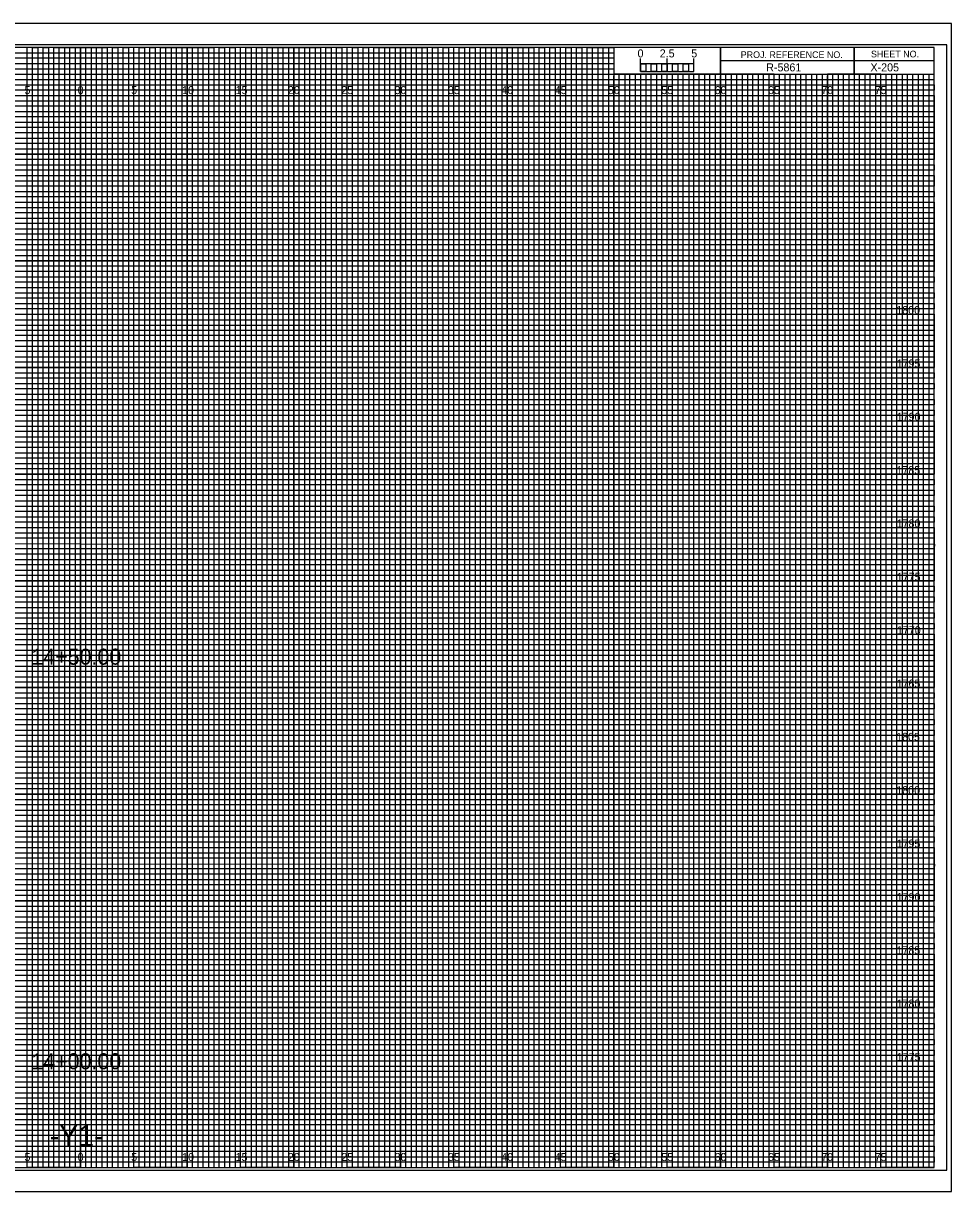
# Model space of a CAD drawing. Extents: x -7 to 162, y -2 to 767.
# Drawn here: x 74.6 to 161.7, y 437.7 to 547.2 of the extents above; entities that cross this region are included whole.
import ezdxf

# ---------------------------------------------------------------- set-up
doc = ezdxf.new("R2010")
doc.units = 0
for name, color, linetype in [('Prop Grid Mask', 7, 'Continuous'), ('Prop XS Alignment Label', 7, 'Continuous'), ('Prop XS Bar Scale Labels', 7, 'Continuous'), ('Prop XS Elevation Labels', 7, 'Continuous'), ('Prop XS Project Number', 7, 'Continuous'), ('Prop XS Sheet Number', 7, 'Continuous'), ('Prop XS Station Labels', 7, 'Continuous'), ('Sheet Cross Section CELL', 7, 'Continuous'), ('Sheet Cross Section Grid Major CELL', 7, 'Continuous'), ('Sheet Cross Section Grid Middle CELL', 7, 'Continuous'), ('Sheet Cross Section Grid Minor 1 CELL', 7, 'Continuous'), ('Sheet Cross Section Grid Minor 2 CELL', 7, 'Continuous'), ('Sheet Cross Section Scale CELL', 7, 'Continuous'), ('Sheet Cutting Line CELL', 7, 'Continuous'), ('Sheet DOT Grid CELL', 7, 'Continuous'), ('Sheet Plot Border Inside CELL', 7, 'Continuous'), ('Sheet Plot Border Outside CELL', 7, 'Continuous')]:
    doc.layers.add(name, color=color, linetype=linetype)

msp = doc.modelspace()

# ---------------------------------------------------------------- linework, layer by layer
at = {"layer": 'Sheet Cross Section CELL'}
for p, q in [((152.5, 545), (152.5, 542.5)), ((152.5, 542.5), (152.5, 545)), ((160, 543.75), (140, 543.75)), ((140, 543.75), (140, 542.5)), ((140, 542.5), (160, 542.5))]:
    msp.add_line(p, q, dxfattribs=at)
for points in [[(160, 545), (0, 545), (0, 440), (160, 440)], [(140, 545), (130, 545), (130, 542.51), (140, 542.51)], [(160, 545), (140, 545), (140, 542.5), (160, 542.5)]]:
    msp.add_lwpolyline(points, close=True, dxfattribs=at)
at = {"layer": 'Sheet Cross Section Grid Major CELL'}
for p, q in [((75, 545), (70, 545)), ((75, 440), (75, 545)), ((85, 545), (80, 545)), ((80, 545), (80, 440)), ((85, 440), (85, 545)), ((95, 545), (90, 545)), ((90, 545), (90, 440)), ((95, 440), (95, 545)), ((105, 545), (100, 545)), ((100, 545), (100, 440)), ((105, 440), (105, 545)), ((115, 545), (110, 545)), ((110, 545), (110, 440)), ((115, 440), (115, 545)), ((125, 545), (120, 545)), ((120, 545), (120, 440)), ((125, 440), (125, 545)), ((130, 545), (130, 440)), ((135, 440), (135, 542.5)), ((145, 542.5), (140, 542.5)), ((140, 542.5), (140, 440)), ((145, 440), (145, 542.5)), ((155, 542.5), (150, 542.5)), ((150, 542.5), (150, 440)), ((155, 440), (155, 542.5)), ((80, 440), (75, 440)), ((90, 440), (85, 440)), ((100, 440), (95, 440)), ((110, 440), (105, 440)), ((120, 440), (115, 440)), ((130, 440), (125, 440)), ((140, 440), (135, 440)), ((150, 440), (145, 440)), ((160, 440), (155, 440)), ((160, 440), (160, 440))]:
    msp.add_line(p, q, dxfattribs=at)
for points in [[(0, 540), (160, 540), (160, 535), (0, 535)], [(0, 530), (160, 530), (160, 525), (0, 525)], [(0, 520), (160, 520), (160, 515), (0, 515)], [(0, 510), (160, 510), (160, 505), (0, 505)], [(0, 500), (160, 500), (160, 495), (0, 495)], [(0, 490), (160, 490), (160, 485), (0, 485)], [(0, 480), (160, 480), (160, 475), (0, 475)], [(0, 470), (160, 470), (160, 465), (0, 465)], [(0, 460), (160, 460), (160, 455), (0, 455)], [(0, 450), (160, 450), (160, 445), (0, 445)]]:
    msp.add_lwpolyline(points, dxfattribs=at)
at = {"layer": 'Sheet Cross Section Grid Middle CELL'}
for points in [[(72.5, 440), (77.5, 440), (77.5, 545), (82.5, 545), (82.5, 440), (87.5, 440), (87.5, 545), (92.5, 545), (92.5, 440), (97.5, 440), (97.5, 545), (102.5, 545), (102.5, 440), (107.5, 440), (107.5, 545), (112.5, 545), (112.5, 440), (117.5, 440), (117.5, 545), (122.5, 545), (122.5, 440), (127.5, 440), (127.5, 545), (129.97, 545), (130, 545), (130, 542.5), (132.5, 542.5), (132.5, 440), (137.5, 440), (137.5, 542.5), (142.5, 542.5), (142.5, 440), (147.5, 440), (147.5, 542.5), (152.5, 542.5), (152.5, 440), (157.5, 440), (157.5, 542.5)], [(0, 542.5), (137.5, 542.5)], [(0, 532.5), (160, 532.5), (160, 537.5), (0, 537.5)], [(0, 522.5), (160, 522.5), (160, 527.5), (0, 527.5)], [(0, 512.5), (160, 512.5), (160, 517.5), (0, 517.5)], [(0, 502.5), (160, 502.5), (160, 507.5), (0, 507.5)], [(0, 492.5), (160, 492.5), (160, 497.5), (0, 497.5)], [(0, 482.5), (160, 482.5), (160, 487.5), (0, 487.5)], [(0, 472.5), (160, 472.5), (160, 477.5), (0, 477.5)], [(0, 462.5), (160, 462.5), (160, 467.5), (0, 467.5)], [(0, 452.5), (160, 452.5), (160, 457.5), (0, 457.5)], [(0, 442.5), (160, 442.5), (160, 447.5), (0, 447.5)]]:
    msp.add_lwpolyline(points, dxfattribs=at)
at = {"layer": 'Sheet Cross Section Grid Minor 1 CELL'}
for p, q in [((0, 544.5), (130, 544.5)), ((130, 544.5), (130, 543.99)), ((130, 543.99), (0, 543.99)), ((0, 543.5), (130, 543.5)), ((130, 543.5), (130, 542.95)), ((130, 542.95), (0, 542.95)), ((0, 542), (160, 542))]:
    msp.add_line(p, q, dxfattribs=at)
for points in [[(0, 541.5), (135, 541.5), (160, 541.5), (160, 541), (0, 541)], [(0, 540.5), (160, 540.5), (160, 539.5), (0, 539.5)], [(0, 539), (160, 539), (160, 538.5), (0, 538.49)], [(0, 538), (160, 538), (160, 537), (0, 537)], [(0, 536.5), (160, 536.5), (160, 536), (0, 536)], [(0, 535.5), (160, 535.5), (160, 534.5), (0, 534.5)], [(0, 534), (160, 534), (160, 533.5), (0, 533.5)], [(0, 533), (160, 533), (160, 532), (0, 532)], [(0, 531.5), (160, 531.5), (160, 531), (0, 531)], [(0, 530.5), (160, 530.5), (160, 529.5), (0, 529.5)], [(0, 529), (160, 529), (160, 528.5), (0, 528.5)], [(0, 528), (160, 528), (160, 526.98), (160, 526.5), (160, 526), (0, 526)], [(0, 527), (160, 527), (160, 526.5), (0, 526.5)], [(0, 525.5), (160, 525.5), (160, 524.5), (0, 524.51)], [(0, 524.51), (160, 524.5), (160, 524), (0, 524)], [(0, 523.5), (160, 523.5), (160, 523), (0, 523)], [(0, 522), (160, 522), (160, 521.5), (0, 521.5)], [(0, 521), (160, 521), (160, 520.5), (0, 520.5)], [(-0.04, 519.45), (160, 519.45), (160, 518.94), (-0.04, 518.94)], [(0, 518.5), (160, 518.5), (160, 518), (0, 518)], [(0, 517), (160, 517), (160, 516.5), (0, 516.5)], [(0, 516), (160, 516), (160, 515.5), (0, 515.5)], [(0, 514.5), (160, 514.5), (160, 514), (0, 514)], [(0, 513.5), (160, 513.5), (160, 513), (0, 513)], [(0, 512), (160, 512), (160, 511.5), (0, 511.5)], [(0, 511), (160, 511), (160, 510.5), (0, 510.5)], [(0, 509.5), (160, 509.5), (160, 508.99), (0, 509)], [(0, 508.5), (160, 508.5), (160, 508), (0, 508)], [(0, 507), (160, 507), (160, 506.5), (0, 506.5)], [(0, 506), (160, 506), (160, 505.5), (0, 505.5)], [(0, 504.5), (160, 504.5), (160, 504), (0, 504)], [(0, 503.5), (160, 503.5), (160, 503), (0, 503)], [(0, 502), (160, 502), (160, 501.5), (0, 501.5)], [(0, 501), (160, 501), (160, 500.5), (0, 500.5)], [(0, 499.5), (160, 499.5), (160, 499), (0, 499)], [(0, 498.5), (160.03, 498.45), (160, 498), (0, 498)], [(0, 497), (160, 497), (160, 496.5), (0, 496.5)], [(0, 496), (160, 496), (160, 495.5), (0, 495.5)], [(0, 494.5), (160, 494.5), (160, 494), (0, 494)], [(0, 493.5), (160, 493.5), (160, 493), (0, 493)], [(0, 492), (160, 492), (160, 491.5), (0, 491.5)], [(0, 491), (160, 491), (160, 490.5), (0, 490.5)], [(0, 489.5), (160, 489.5), (160, 489), (0, 489)], [(0, 488.5), (160, 488.5), (160, 488), (0, 488)], [(0, 487), (160, 487), (160, 486.5), (0, 486.5)], [(0, 486), (160, 486), (160, 485.5), (0, 485.5)], [(0, 484.5), (160, 484.5), (160, 484), (0, 484)], [(0, 483.5), (160, 483.5), (160, 483), (0, 483)], [(0, 482), (160, 482), (160, 481.5), (0, 481.5)], [(0, 481), (160, 481), (160, 480.5), (0, 480.5)], [(0, 479.5), (160, 479.5), (160, 478.99), (0, 479)], [(0, 478.5), (160, 478.5), (160, 478), (0, 478)], [(0, 477), (160, 477), (160, 476.5), (0, 476.5)], [(0, 476), (160, 476), (160, 475.5), (0, 475.5)], [(0, 474.5), (160, 474.5), (160, 474), (0, 474)], [(0, 473.5), (160, 473.5), (160, 473), (0, 473)], [(0, 472), (160, 472), (160, 471.5), (0, 471.5)], [(0, 471), (160, 471), (160, 470.5), (0, 470.5)], [(0, 469.5), (160, 469.5), (160, 469), (0, 469)], [(0, 468.5), (160.03, 468.45), (160, 468), (0, 468)], [(0, 467), (160, 467), (160, 466.5), (0, 466.5)], [(0, 466), (160, 466), (160, 465.5), (0, 465.5)], [(0, 464.5), (160, 464.5), (160, 464), (0, 464)], [(0, 463.5), (160, 463.5), (160, 463), (0, 463)], [(0, 462), (160, 462), (160, 461.5), (0, 461.5)], [(0, 461), (160, 461), (160, 460.5), (0, 460.5)], [(0, 459.5), (160, 459.5), (160, 459), (0, 459)], [(0, 458.5), (160, 458.5), (160, 458), (0, 458)], [(0, 457), (160, 457), (160, 456.5), (0, 456.5)], [(0, 456), (160, 456), (160, 455.5), (0, 455.5)], [(0, 454.5), (160, 454.5), (160, 454), (0, 454)], [(0, 453.5), (160, 453.5), (160, 453), (0, 453)], [(0, 452), (160, 452), (160, 451.5), (0, 451.5)], [(0, 451), (160, 451), (160, 450.5), (0, 450.5)], [(0, 449.5), (160, 449.5), (160, 449), (0, 449)], [(0, 448.5), (160, 448.5), (160, 448), (0, 448)], [(0, 447), (160, 447), (160, 446.5), (0, 446.5)], [(0, 446), (160, 446), (160, 445.5), (0, 445.5)], [(0, 444.5), (160, 444.5), (160, 444), (0, 444)], [(0, 443.5), (160, 443.5), (160, 443), (0, 443)], [(0, 442), (160, 442), (160, 441.5), (0, 441.5)], [(0, 441), (160, 441), (160, 440.5), (0, 440.5)]]:
    msp.add_lwpolyline(points, dxfattribs=at)
at = {"layer": 'Sheet Cross Section Grid Minor 2 CELL'}
for p, q in [((133.5, 542.5), (133, 542.5)), ((133, 542.5), (133, 440)), ((133.5, 440), (133.5, 542.5)), ((134.5, 542.5), (134, 542.5)), ((134, 542.5), (134, 440)), ((134.5, 440), (134.5, 542.5)), ((133, 440), (132.5, 440)), ((134, 440), (133.5, 440))]:
    msp.add_line(p, q, dxfattribs=at)
for points in [[(75, 440), (75.5, 440), (75.5, 545), (76, 545), (76, 440)], [(76, 440), (76.5, 440), (76.5, 545), (77, 545), (77, 440)], [(77.5, 440), (78, 440), (78, 545), (78.5, 545), (78.5, 440)], [(78.5, 440), (79, 440), (79, 545), (79.5, 545), (79.5, 440)], [(80, 440), (80.5, 440), (80.5, 545), (81, 545), (81, 440)], [(81, 440), (81.5, 440), (81.5, 545), (82, 545), (82, 440)], [(82.5, 440), (83, 440), (83, 545), (83.5, 545), (83.5, 440)], [(83.5, 440), (84, 440), (84, 545), (84.5, 545), (84.5, 440)], [(85, 440), (85.5, 440), (85.5, 545), (86, 545), (86, 440)], [(86, 440), (86.5, 440), (86.5, 545), (87, 545), (87, 440)], [(87.5, 440), (88, 440), (88, 545), (88.5, 545), (88.5, 440)], [(88.5, 440), (89, 440), (89, 545), (89.5, 545), (89.5, 440)], [(90, 440), (90.5, 440), (90.5, 545), (91, 545), (91, 440)], [(91, 440), (91.5, 440), (91.5, 545), (92, 545), (92, 440)], [(92.5, 440), (93, 440), (93, 545), (93.5, 545), (93.5, 440)], [(93.5, 440), (94, 440), (94, 545), (94.5, 545), (94.5, 440)], [(95, 440), (95.5, 440), (95.5, 545), (96, 545), (96, 440)], [(96, 440), (96.5, 440), (96.5, 545), (97, 545), (97, 440)], [(97.5, 440), (98, 440), (98, 545), (98.5, 545), (98.5, 440)], [(98.5, 440), (99, 440), (99, 545), (99.5, 545), (99.5, 440)], [(100, 440), (100.5, 440), (100.5, 545), (101, 545), (101, 440)], [(101, 440), (101.5, 440), (101.5, 545), (102, 545), (102, 440)], [(102.5, 440), (103, 440), (103, 545), (103.5, 545), (103.5, 440)], [(103.5, 440), (104, 440), (104, 545), (104.5, 545), (104.5, 440)], [(105, 440), (105.5, 440), (105.5, 545), (106, 545), (106, 440)], [(106, 440), (106.5, 440), (106.5, 545), (107, 545), (107, 440)], [(107.5, 440), (108, 440), (108, 545), (108.5, 545), (108.5, 440)], [(108.5, 440), (109, 440), (109, 545), (109.5, 545), (109.5, 440)], [(110, 440), (110.5, 440), (110.5, 545), (111, 545), (111, 440)], [(111, 440), (111.5, 440), (111.5, 545), (112, 545), (112, 440)], [(112.5, 440), (113, 440), (113, 545), (113.5, 545), (113.5, 440)], [(113.5, 440), (114, 440), (114, 545), (114.5, 545), (114.5, 440)], [(115, 440), (115.5, 440), (115.5, 545), (116, 545), (116, 440)], [(116, 440), (116.5, 440), (116.5, 545), (117, 545), (117, 440)], [(117.5, 440), (118, 440), (118, 545), (118.5, 545), (118.5, 440)], [(118.5, 440), (119, 440), (119, 545), (119.5, 545), (119.5, 440)], [(120, 440), (120.5, 440), (120.5, 545), (121, 545), (121, 440)], [(121, 440), (121.5, 440), (121.5, 545), (122, 545), (122, 440)], [(122.5, 440), (123, 440), (123, 545), (123.5, 545), (123.5, 440)], [(123.5, 440), (124, 440), (124, 545), (124.5, 545), (124.5, 440)], [(125, 440), (125.5, 440), (125.5, 545), (126, 545), (126, 440)], [(126, 440), (126.5, 440), (126.5, 545), (127, 545), (127, 440)], [(127.5, 440), (128, 440), (128, 545), (128.5, 545), (128.5, 440)], [(128.5, 440), (129, 440), (129, 545), (129.5, 545), (129.5, 440)], [(130, 440), (130.5, 440), (130.5, 542.5), (131.01, 542.5), (131.01, 440)], [(131, 440), (131.5, 440), (131.5, 542.5), (132, 542.5), (132, 440)], [(135, 440), (135.49, 440), (135.49, 542.5), (136, 542.5), (136, 440)], [(136, 440), (136.5, 440), (136.5, 542.5), (137.03, 542.5), (137.03, 440)], [(137.5, 440), (138, 440), (138, 542.5), (138.5, 542.5), (138.5, 440)], [(138.5, 440), (139, 440), (139, 542.5), (139.5, 542.5), (139.5, 440)], [(140, 440), (140.5, 440), (140.5, 542.5), (141, 542.5), (141, 440)], [(141, 440), (141.5, 440), (141.5, 542.5), (142, 542.5), (142, 440)], [(142.5, 440), (143, 440), (143, 542.5), (143.5, 542.5), (143.5, 440)], [(143.5, 440), (144, 440), (144, 542.5), (144.5, 542.5), (144.5, 440)], [(145, 440), (145.5, 440), (145.5, 542.5), (146, 542.5), (146, 440)], [(146, 440), (146.5, 440), (146.5, 542.5), (147, 542.5), (147, 440)], [(147.5, 440), (148, 440), (148, 542.5), (148.5, 542.5), (148.5, 440)], [(148.5, 440), (149, 440), (149, 542.5), (149.5, 542.5), (149.5, 440)], [(150, 440), (150.5, 440), (150.5, 542.5), (151, 542.5), (151, 440)], [(151, 440), (151.5, 440), (151.5, 542.5), (152, 542.5), (152, 440)], [(152.5, 440), (153, 440), (153, 542.5), (153.5, 542.5), (153.5, 440)], [(153.5, 440), (154, 440), (154, 542.5), (154.5, 542.5), (154.5, 440)], [(155, 440), (155.5, 440), (155.5, 542.5), (156, 542.5), (156, 440)], [(156, 440), (156.5, 440), (156.5, 542.5), (157, 542.5), (157, 440)], [(157.5, 440), (158, 440), (158, 542.5), (158.5, 542.5), (158.5, 440)], [(158.5, 440), (159, 440), (159, 542.5), (159.5, 542.5), (159.5, 440)]]:
    msp.add_lwpolyline(points, dxfattribs=at)
at = {"layer": 'Sheet Cross Section Scale CELL'}
for p, q in [((132.5, 542.75), (132.5, 543.95)), ((132.5, 543.45), (132.5, 543.95)), ((135, 542.75), (135, 543.95)), ((137.5, 542.75), (137.5, 543.95)), ((137.5, 543.45), (137.5, 543.95))]:
    msp.add_line(p, q, dxfattribs=at)
for points in [[(137.5, 543.45), (132.5, 543.45), (132.5, 542.75), (137.5, 542.75)], [(132.5, 543.45), (133, 543.45), (133, 542.75), (132.5, 542.75)], [(133.5, 543.45), (134, 543.45), (134, 542.75), (133.5, 542.75)], [(134.5, 543.45), (135, 543.45), (135, 542.75), (134.5, 542.75)], [(135.5, 543.45), (136, 543.45), (136, 542.75), (135.5, 542.75)], [(136.5, 543.45), (137, 543.45), (137, 542.75), (136.5, 542.75)]]:
    msp.add_lwpolyline(points, close=True, dxfattribs=at)
at = {"layer": 'Sheet Cutting Line CELL'}
for p, q in [((161.65, 547.25), (-6.7, 547.25)), ((-6.7, 437.75), (161.65, 437.75))]:
    msp.add_line(p, q, dxfattribs=at)
at = {"layer": 'Sheet DOT Grid CELL'}
for p, q in [((75, 440), (75, 545)), ((80, 440), (80, 545)), ((85, 440), (85, 545)), ((90, 440), (90, 545)), ((95, 440), (95, 545)), ((100, 440), (100, 545)), ((105, 440), (105, 545)), ((110, 440), (110, 545)), ((115, 440), (115, 545)), ((120, 440), (120, 545)), ((125, 440), (125, 545)), ((130, 440), (130, 542.34)), ((135, 440), (135, 542.34)), ((140, 440), (140, 542.34)), ((145, 440), (145, 542.34)), ((150, 440), (150, 542.34)), ((155, 440), (155, 542.34)), ((0, 540), (160, 540)), ((0, 535), (160, 535)), ((0, 530), (160, 530)), ((0, 525), (160, 525)), ((0, 520), (160, 520)), ((0, 515), (160, 515)), ((0, 510), (160, 510)), ((0, 505), (160, 505)), ((0, 500), (160, 500)), ((0, 495), (160, 495)), ((0, 490), (160, 490)), ((0, 485), (160, 485)), ((0, 480), (160, 480)), ((0, 475), (160, 475)), ((0, 470), (160, 470)), ((0, 465), (160, 465)), ((0, 460), (160, 460)), ((0, 455), (160, 455)), ((0, 450), (160, 450)), ((0, 445), (160, 445))]:
    msp.add_line(p, q, dxfattribs=at)
at = {"layer": 'Sheet Plot Border Inside CELL'}
msp.add_lwpolyline([(-5.4, 439.75), (161.2, 439.75), (161.2, 545.25), (-5.4, 545.25)], close=True, dxfattribs=at)
at = {"layer": 'Sheet Plot Border Outside CELL'}
msp.add_lwpolyline([(-6.7, 437.75), (161.65, 437.75), (161.65, 547.25), (-6.7, 547.25)], close=True, dxfattribs=at)

# ---------------------------------------------------------------- texts
at = {"layer": 'Prop Grid Mask'}
for s, p in [('5', (74.74, 540.62)), ('0', (79.73, 540.62)), ('0', (79.73, 540.62)), ('5', (84.74, 540.62)), ('10', (89.52, 540.62)), ('15', (94.53, 540.62)), ('20', (99.43, 540.62)), ('25', (104.44, 540.62)), ('30', (109.43, 540.62)), ('35', (114.44, 540.62)), ('40', (119.43, 540.62)), ('45', (124.44, 540.62)), ('50', (129.43, 540.62)), ('55', (134.44, 540.62)), ('60', (139.43, 540.62)), ('65', (144.44, 540.62)), ('70', (149.43, 540.62)), ('75', (154.44, 540.62)), ('5', (74.74, 440.62)), ('0', (79.73, 440.62)), ('0', (79.73, 440.62)), ('5', (84.74, 440.62)), ('10', (89.52, 440.62)), ('15', (94.53, 440.62)), ('20', (99.43, 440.62)), ('25', (104.44, 440.62)), ('30', (109.43, 440.62)), ('35', (114.44, 440.62)), ('40', (119.43, 440.62)), ('45', (124.44, 440.62)), ('50', (129.43, 440.62)), ('55', (134.44, 440.62)), ('60', (139.43, 440.62)), ('65', (144.44, 440.62)), ('70', (149.43, 440.62)), ('75', (154.44, 440.62))]:
    msp.add_text(s, height=0.75, dxfattribs=at).set_placement(p)
at = {"layer": 'Prop XS Alignment Label'}
msp.add_text('-Y1-', height=2, dxfattribs=at).set_placement((77.11, 442))
at = {"layer": 'Prop XS Bar Scale Labels'}
for s, p in [('2.5', (134.29, 544.06)), ('5', (137.24, 544.06))]:
    msp.add_text(s, height=0.75, dxfattribs=at).set_placement(p)
at = {"layer": 'Prop XS Elevation Labels'}
for s, p in [('1800', (156.46, 520)), ('1795', (156.49, 515)), ('1790', (156.5, 510)), ('1785', (156.48, 505)), ('1780', (156.49, 500)), ('1775', (156.51, 495)), ('1770', (156.52, 490)), ('1765', (156.49, 485)), ('1805', (156.45, 480)), ('1800', (156.46, 475)), ('1795', (156.49, 470)), ('1790', (156.5, 465)), ('1785', (156.48, 460)), ('1780', (156.49, 455)), ('1775', (156.51, 450))]:
    msp.add_text(s, height=0.75, dxfattribs=at).set_placement(p)
at = {"layer": 'Prop XS Project Number'}
msp.add_text('R-5861', height=0.75, dxfattribs=at).set_placement((144.27, 542.75))
at = {"layer": 'Prop XS Sheet Number'}
msp.add_text('X-205', height=0.75, dxfattribs=at).set_placement((154.04, 542.75))
at = {"layer": 'Prop XS Station Labels'}
for s, p in [('14+50.00', (75.39, 487.14)), ('14+00.00', (75.39, 449.22))]:
    msp.add_text(s, height=1.5, dxfattribs=at).set_placement(p)
at = {"layer": 'Sheet Cross Section CELL'}
for s, p in [('PROJ. REFERENCE NO.', (141.88, 544)), ('SHEET NO.', (154.09, 544.06))]:
    msp.add_text(s, height=0.625, dxfattribs=at).set_placement(p)
at = {"layer": 'Sheet Cross Section Scale CELL'}
msp.add_text('0', height=0.75, dxfattribs=at).set_placement((132.21, 544.06))

doc.saveas('drawing.dxf')
